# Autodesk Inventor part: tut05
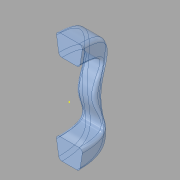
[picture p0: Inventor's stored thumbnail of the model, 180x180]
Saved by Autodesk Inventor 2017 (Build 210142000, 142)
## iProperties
Created: 2015-03
Part Number: tut05
Material: Generic
Document SubType Name: Modeling
Designer: Sandeep
Density: 1 g/cm^3
Appearance: Blue - Glazing
Mass: 996.637 g
Surface Area: 881.078 cm^2
Volume: 996.637 cm^3
Author: Sandeep
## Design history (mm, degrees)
sketch "Sketch1"
  geometry: L1 (-20, 50)-(20, 50); L2 (30, 60)-(30, 70); L3 (-30, 60)-(-30, 70); L4 (0, -9.695)-(0, 120.745); A1 r 45 centre (0, 36.459) between (30, 70) and (-30, 70); A2 r 10 centre (-20, 60) between (-30, 60) and (-20, 50); A3 r 10 centre (20, 60) between (20, 50) and (30, 60); 2 further points
  constraints: 8 end point, 6 point on circle, 4 point on line, 4 tangent, 3 centre point, 2 vertical, 1 horizontal, 1 perpendicular, 1 other
  dimensions: "d0" = 60 distance between parallel lines of L2 L3; "d1" = 70 vertical distance of point (0, 0) L2.end; "d2" = 20 distance of point (30, 50) L2.end; "d3" = 45 radius of A1; "d4" = 10 radius of A2; "d5" = 10 radius of A3
sketch "Sketch2"
  geometry: L1 (30.844, 175)-(-30.844, 175); L2 (-40.728, 163.479)-(-33.805, 118.479); L3 (-23.921, 110)-(23.921, 110); L4 (33.805, 118.479)-(40.728, 163.479); L5 (0, 0)-(0, 325.346); A1 r 10 centre (30.844, 165) between (40.728, 163.479) and (30.844, 175); A2 r 10 centre (-30.844, 165) between (-30.844, 175) and (-40.728, 163.479); A3 r 10 centre (-23.921, 120) between (-33.805, 118.479) and (-23.921, 110); A4 r 10 centre (23.921, 120) between (23.921, 110) and (33.805, 118.479); 4 further points
  constraints: 10 end point, 8 point on circle, 8 point on line, 8 tangent, 4 centre point, 3 equal radius, 1 horizontal, 1 parallel, 1 vertical, 1 other
  dimensions: "d6" = 65 distance of point (-32.5, 110) point (32.5, 110); "d7" = 65 distance between parallel lines of L1 L3; "d8" = 85 distance of point (42.5, 175) point (-42.5, 175); "d9" = 175 distance from line of L5.start L1; "d10" = 10 radius of A1
sketch "Sketch3"
  geometry: 1 further point
sketch "Sketch4"
  geometry: 1 further point
sketch "Sketch5"
  geometry: L1 (30.844, -110)-(-30.844, -110); L2 (-40.728, -121.521)-(-33.805, -166.521); L3 (-23.921, -175)-(23.921, -175); L4 (33.805, -166.521)-(40.728, -121.521); L5 (0, 0)-(0, -235.653); A1 r 10 centre (-23.921, -165) between (-33.805, -166.521) and (-23.921, -175); A2 r 10 centre (23.921, -165) between (23.921, -175) and (33.805, -166.521); A3 r 10 centre (30.844, -120) between (40.728, -121.521) and (30.844, -110); A4 r 10 centre (-30.844, -120) between (-30.844, -110) and (-40.728, -121.521); 4 further points
  constraints: 10 end point, 8 point on circle, 8 point on line, 8 tangent, 4 centre point, 3 equal radius, 1 horizontal, 1 parallel, 1 vertical, 1 other
  dimensions: "d11" = 85 distance of point (42.5, -110) point (-42.5, -110); "d12" = 65 distance of point (-32.5, -175) point (32.5, -175); "d13" = 65 distance between parallel lines of L1 L3; "d14" = 175 distance from line of L5.start L3; "d15" = 10 radius of A1
loft "Loft1" sketch "Sketch5" dims "d16" = 50, "d17" = 90 deg, "d18" = 0, "d19" = 90 deg, "d20" = 50, "d21" = 90 deg
body "Solid1"
